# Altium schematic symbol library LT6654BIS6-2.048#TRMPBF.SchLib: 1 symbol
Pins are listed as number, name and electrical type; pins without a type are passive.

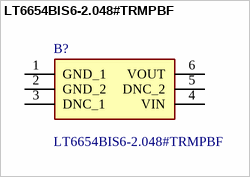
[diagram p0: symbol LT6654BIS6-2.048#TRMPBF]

## LT6654BIS6-2.048#TRMPBF
designator B?
LINEAR TECHNOLOGY - LT6654BIS6-2.048#TRMPBF - Voltage Reference, Series - Fixed, LT6654 Series, 2.048V reference, 0.1 %, +/- 10ppm/C, TSOT-23-6; Manufacturer_Name: Analog Devices; Geometry.Height: 1mm
footprint SOT95P280X100-6N
pins: 1 GND_1, 2 GND_2, 3 DNC_1, 4 VIN, 5 DNC_2, 6 VOUT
